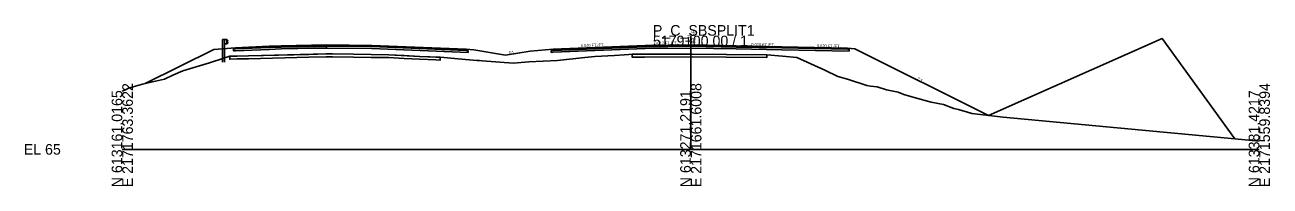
# Model space of a CAD drawing. Extents: x -26 to 1303, y -3010 to 12033.
# Drawn here: x -25.7 to 302.8, y 3990.3 to 4032.8 of the extents above; entities that cross this region are included whole.
import ezdxf

# ---------------------------------------------------------------- set-up
doc = ezdxf.new("R2010")
doc.units = 0
for name, color, linetype in [('RD_GPK_XS_Cell', 7, 'Continuous'), ('RD_PD_Final_TrvlWay', 7, 'Continuous'), ('RD_Sketch10', 7, 'Continuous'), ('RD_XS_Base', 7, 'Continuous'), ('RD_XS_ExGround', 7, 'Continuous'), ('RD_XS_ExPaveRet', 7, 'Continuous'), ('RD_XS_GR', 7, 'Continuous'), ('RD_XS_Greenside', 7, 'Continuous'), ('RD_XS_Pave', 7, 'Continuous'), ('RD_XS_PaveOvlay_CP', 7, 'Continuous'), ('RD_XS_TieSlope', 7, 'Continuous'), ('RD_XS_TX_Elev_EX', 7, 'Continuous'), ('RD_XS_TX_Elev_PR', 7, 'Continuous'), ('RD_XS_TX_Slope', 7, 'Continuous')]:
    doc.layers.add(name, color=color, linetype=linetype)

msp = doc.modelspace()

# ---------------------------------------------------------------- linework, layer by layer
at = {"layer": 'RD_GPK_XS_Cell'}
for p, q in [((150, 4000), (150, 4030)), ((0, 4000), (150, 4000)), ((150, 4000), (300, 4000))]:
    msp.add_line(p, q, dxfattribs=at)
at = {"layer": 'RD_PD_Final_TrvlWay'}
for p, q in [((26.94, 4026.6), (26.44, 4026.56)), ((26.44, 4026.56), (26.44, 4022.99)), ((26.94, 4022.99), (26.94, 4026.6))]:
    msp.add_line(p, q, dxfattribs=at)
at = {"layer": 'RD_Sketch10'}
msp.add_lwpolyline([(228.57, 4008.93), (274.33, 4029.26), (293.53, 4002.78)], dxfattribs=at)
at = {"layer": 'RD_XS_Base'}
for p, q in [((29.75, 4026.51), (29.38, 4026.49)), ((29.38, 4026.49), (29.38, 4026.36)), ((29.38, 4026.36), (29.38, 4025.99)), ((29.38, 4025.99), (29.75, 4026.01)), ((29.88, 4026.51), (29.75, 4026.51)), ((29.75, 4026.01), (29.88, 4026.01)), ((38.75, 4026.87), (29.88, 4026.51)), ((29.88, 4026.01), (38.75, 4026.37)), ((41.88, 4026.99), (38.75, 4026.87)), ((38.75, 4026.37), (41.88, 4026.49)), ((50.75, 4027.17), (41.88, 4026.99)), ((41.88, 4026.49), (50.75, 4026.67)), ((53.88, 4027.23), (50.75, 4027.17)), ((50.75, 4026.67), (53.88, 4026.73)), ((53.88, 4027.35), (53.88, 4027.39)), ((53.88, 4027.39), (53.88, 4027.22)), ((53.88, 4027.23), (53.88, 4027.39)), ((53.88, 4027.39), (53.88, 4027.39)), ((53.88, 4027.39), (53.88, 4027.39)), ((53.88, 4027.39), (53.88, 4026.73)), ((53.88, 4027.23), (53.88, 4027.35)), ((53.88, 4027.1), (53.88, 4027.23)), ((65.88, 4027.1), (53.88, 4027.23)), ((53.88, 4026.73), (53.88, 4027.23)), ((53.88, 4027.23), (53.88, 4027.23)), ((53.88, 4027.23), (53.88, 4027.23)), ((53.88, 4027.22), (53.88, 4026.73)), ((53.88, 4026.73), (53.88, 4027.1)), ((53.88, 4026.73), (65.88, 4026.6)), ((53.88, 4026.73), (53.88, 4026.73)), ((90.75, 4026.1), (65.88, 4027.1)), ((65.88, 4026.6), (91.25, 4025.58)), ((67.88, 4027.02), (67.88, 4027.02)), ((67.88, 4026.52), (67.88, 4026.52)), ((91.25, 4026.08), (90.75, 4026.1)), ((90.75, 4026.1), (90.75, 4026.1)), ((91.25, 4025.58), (91.25, 4026.08)), ((91.25, 4026.08), (91.25, 4026.08)), ((91.25, 4025.58), (91.25, 4025.58)), ((91.25, 4025.58), (91.25, 4025.58)), ((113.15, 4026.09), (113.65, 4026.11)), ((113.15, 4025.59), (113.15, 4026.09)), ((113.15, 4026.09), (113.15, 4026.09)), ((113.65, 4025.61), (113.15, 4025.59)), ((113.15, 4025.59), (113.15, 4025.59)), ((113.15, 4025.59), (113.15, 4025.59)), ((113.65, 4026.11), (138, 4027.09)), ((138, 4026.59), (113.65, 4025.61)), ((113.65, 4026.11), (113.65, 4026.11)), ((113.65, 4025.61), (113.65, 4025.61)), ((136, 4027.01), (136, 4027.01)), ((136, 4026.51), (136, 4026.51)), ((138, 4027.09), (150, 4027.23)), ((150, 4026.73), (138, 4026.59)), ((150, 4027.23), (150, 4027.39)), ((150, 4027.39), (150, 4027.39)), ((150, 4027.39), (150, 4027.39)), ((150, 4027.39), (150, 4026.73)), ((150, 4027.23), (150, 4027.23)), ((162, 4026.99), (150, 4027.23)), ((150, 4027.23), (150, 4027.23)), ((150, 4027.23), (150, 4026.73)), ((150, 4026.73), (150, 4026.73)), ((150, 4026.73), (162, 4026.49)), ((174, 4026.75), (162, 4026.99)), ((162, 4026.99), (162, 4026.99)), ((162, 4026.49), (162, 4026.49)), ((162, 4026.49), (174, 4026.25)), ((191.3, 4026.41), (174, 4026.75)), ((174, 4026.75), (174, 4026.75)), ((174, 4026.25), (174, 4026.25)), ((174, 4026.25), (191.8, 4025.9)), ((191.8, 4026.4), (191.3, 4026.41)), ((191.3, 4026.41), (191.3, 4026.41)), ((191.8, 4025.9), (191.8, 4026.4)), ((191.8, 4026.4), (191.8, 4026.4))]:
    msp.add_line(p, q, dxfattribs=at)
at = {"layer": 'RD_XS_ExGround'}
msp.add_lwpolyline([(0, 4015.32), (0.85, 4015.73), (1.68, 4016.13), (5.29, 4017.16), (7.99, 4017.79), (11.15, 4018.52), (13.38, 4019.57), (15.98, 4020.68), (23, 4022.87), (26.77, 4024.03), (28.34, 4024.55), (30.34, 4024.61), (33.34, 4024.68), (53.81, 4025.19), (61.04, 4025.09), (70.3, 4024.96), (78.39, 4024.54), (83.89, 4024.3), (88.61, 4023.91), (93.52, 4023.47), (94.27, 4023.41), (94.92, 4023.36), (103.13, 4022.78), (107.3, 4023.07), (114.79, 4023.47), (122.03, 4024.26), (124.72, 4024.5), (129.84, 4024.81), (132.42, 4024.96), (133.67, 4025.03), (134.5, 4025.08), (135.83, 4025.09), (137.82, 4025.09), (150.34, 4025.14), (159.37, 4025.06), (170.02, 4024.96), (174.2, 4024.6), (177.94, 4024.23), (185.35, 4020.86), (188.79, 4019.26), (191.3, 4018.5), (196.48, 4016.84), (197.45, 4016.66), (199.13, 4016.49), (201.64, 4015.74), (204.74, 4015.13), (206.23, 4014.5), (208.95, 4013.7), (213.39, 4012.49), (216.7, 4011.88), (219.42, 4010.81), (220.61, 4010.5), (220.64, 4010.5), (223.87, 4009.52), (224.17, 4009.47), (232.37, 4008.47), (293.53, 4002.78), (300, 4002.17)], dxfattribs=at)
at = {"layer": 'RD_XS_ExPaveRet'}
for points in [[(83.89, 4024.3), (83.89, 4024.3), (83.89, 4023.83), (83.89, 4023.55), (83.89, 4023.55), (83.89, 4023.55), (82.7, 4023.6), (78.39, 4023.79), (74.39, 4024), (70.3, 4024.21), (65.63, 4024.28), (61.04, 4024.34), (55.44, 4024.42), (53.81, 4024.44), (49.2, 4024.32), (33.34, 4023.93), (30.34, 4023.86), (28.34, 4023.8), (28.34, 4023.8), (28.34, 4023.8), (28.34, 4023.8), (28.34, 4023.8), (28.34, 4023.8), (28.34, 4024.27), (28.34, 4024.55), (28.34, 4024.55), (28.34, 4024.55), (28.34, 4024.55), (28.34, 4024.55), (28.34, 4024.55), (30.34, 4024.61), (33.34, 4024.68), (49.2, 4025.07), (53.81, 4025.19), (55.44, 4025.17), (61.04, 4025.09), (65.63, 4025.03), (70.3, 4024.96), (74.39, 4024.75), (78.39, 4024.54), (82.7, 4024.35), (83.89, 4024.3), (83.89, 4024.3)], [(82.7, 4024.35), (78.39, 4024.54), (74.39, 4024.75), (70.3, 4024.96), (65.63, 4025.03), (61.04, 4025.09), (55.44, 4025.17), (53.81, 4025.19), (49.2, 4025.07), (33.34, 4024.68), (30.34, 4024.61), (28.34, 4024.55), (28.34, 4024.55), (28.34, 4024.55), (28.34, 4024.55), (28.34, 4024.27), (28.34, 4023.8), (28.34, 4023.8), (28.34, 4023.8), (28.34, 4023.8), (30.34, 4023.86), (33.34, 4023.93), (49.2, 4024.32), (53.81, 4024.44), (55.44, 4024.42), (61.04, 4024.34), (65.63, 4024.28), (70.3, 4024.21), (74.39, 4024), (78.39, 4023.79), (82.7, 4023.6), (83.89, 4023.55), (83.89, 4023.55), (83.89, 4023.83), (83.89, 4024.3), (83.89, 4024.3), (82.7, 4024.35)], [(170.02, 4024.96), (159.37, 4025.06), (159.37, 4025.06), (150.34, 4025.14), (137.82, 4025.09), (137.82, 4025.09), (135.83, 4025.09), (134.5, 4025.08), (134.5, 4025.08), (134.5, 4025.08), (134.5, 4024.33), (134.5, 4024.33), (135.83, 4024.34), (137.82, 4024.34), (137.82, 4024.34), (150.34, 4024.39), (159.37, 4024.31), (159.37, 4024.31), (170.02, 4024.21), (170.02, 4024.21), (170.02, 4024.96), (170.02, 4024.96), (170.02, 4024.96)], [(170.02, 4024.96), (159.37, 4025.06), (150.34, 4025.14), (137.82, 4025.09), (135.83, 4025.09), (134.5, 4025.08), (134.5, 4025.08), (134.5, 4024.33), (134.5, 4024.33), (135.83, 4024.34), (137.82, 4024.34), (150.34, 4024.39), (159.37, 4024.31), (170.02, 4024.21), (170.02, 4024.96)]]:
    msp.add_lwpolyline(points, dxfattribs=at)
at = {"layer": 'RD_XS_GR'}
for p, q in [((26.44, 4026.56), (26.44, 4028.99)), ((26.44, 4028.99), (26.69, 4028.99)), ((26.69, 4028.99), (26.94, 4028.99)), ((26.94, 4028.99), (26.94, 4026.6)), ((26.94, 4027.83), (26.94, 4028.99)), ((26.94, 4028.99), (27.61, 4028.99)), ((27.61, 4027.83), (26.94, 4027.83)), ((27.61, 4028.99), (27.61, 4027.83)), ((27.68, 4028.92), (27.61, 4028.99)), ((27.61, 4028.99), (27.61, 4028.69)), ((27.61, 4028.69), (27.61, 4027.83)), ((27.61, 4028.41), (27.81, 4028.62)), ((27.68, 4028.33), (27.61, 4028.41)), ((27.61, 4027.83), (27.81, 4028.04)), ((27.88, 4028.7), (27.68, 4028.92)), ((27.88, 4028.12), (27.68, 4028.33)), ((27.81, 4028.62), (27.88, 4028.7)), ((27.81, 4028.04), (27.88, 4028.12)), ((26.94, 4026.6), (26.44, 4026.56))]:
    msp.add_line(p, q, dxfattribs=at)
at = {"layer": 'RD_XS_Greenside'}
for p, q in [((24.13, 4026.37), (6.08, 4017.35)), ((92.75, 4026.26), (101.12, 4024.86)), ((107.65, 4025.95), (101.12, 4024.86)), ((193.3, 4026.57), (228.57, 4008.93))]:
    msp.add_line(p, q, dxfattribs=at)
at = {"layer": 'RD_XS_Pave'}
for p, q in [((38.75, 4027.19), (29.88, 4026.83)), ((38.75, 4027.03), (29.88, 4026.67)), ((29.88, 4026.67), (38.75, 4027.03)), ((29.88, 4026.51), (38.75, 4026.87)), ((29.88, 4026.83), (29.88, 4026.79)), ((29.88, 4026.79), (29.88, 4026.67)), ((29.88, 4026.67), (29.88, 4026.63)), ((29.88, 4026.63), (29.88, 4026.51)), ((41.88, 4027.31), (38.75, 4027.19)), ((41.88, 4027.15), (38.75, 4027.03)), ((38.75, 4027.03), (41.88, 4027.15)), ((38.75, 4026.87), (41.88, 4026.99)), ((50.75, 4027.49), (41.88, 4027.31)), ((50.75, 4027.33), (41.88, 4027.15)), ((41.88, 4027.15), (50.75, 4027.33)), ((41.88, 4026.99), (50.75, 4027.17)), ((53.88, 4027.55), (50.75, 4027.49)), ((53.88, 4027.39), (50.75, 4027.33)), ((50.75, 4027.33), (53.88, 4027.39)), ((50.75, 4027.17), (53.88, 4027.23)), ((65.88, 4027.41), (53.88, 4027.55)), ((53.88, 4027.55), (53.88, 4027.55)), ((53.88, 4027.35), (53.88, 4027.39)), ((53.88, 4027.39), (53.88, 4027.35)), ((65.88, 4027.25), (53.88, 4027.39)), ((53.88, 4027.39), (53.88, 4027.39)), ((53.88, 4027.39), (53.88, 4027.23)), ((53.88, 4027.23), (53.88, 4027.39)), ((53.88, 4027.39), (53.88, 4027.39)), ((53.88, 4027.39), (53.88, 4027.39)), ((53.88, 4027.39), (53.88, 4027.39)), ((53.88, 4027.39), (65.88, 4027.25)), ((53.88, 4027.23), (53.88, 4027.35)), ((53.88, 4027.35), (53.88, 4027.23)), ((53.88, 4027.23), (65.88, 4027.1)), ((53.88, 4027.23), (53.88, 4027.23)), ((90.75, 4026.42), (65.88, 4027.41)), ((90.75, 4026.26), (65.88, 4027.25)), ((65.88, 4027.25), (90.75, 4026.26)), ((65.88, 4027.1), (90.75, 4026.1)), ((67.88, 4027.33), (67.88, 4027.33)), ((67.88, 4027.17), (67.88, 4027.17)), ((67.88, 4027.17), (67.88, 4027.17)), ((67.88, 4027.02), (67.88, 4027.02)), ((90.75, 4026.26), (90.75, 4026.42)), ((90.75, 4026.42), (90.75, 4026.42)), ((90.75, 4026.1), (90.75, 4026.26)), ((90.75, 4026.26), (90.75, 4026.26)), ((90.75, 4026.26), (90.75, 4026.26)), ((90.75, 4026.26), (90.75, 4026.26)), ((90.75, 4026.1), (90.75, 4026.1)), ((90.75, 4026.1), (90.75, 4026.1)), ((138, 4027.41), (113.65, 4026.43)), ((138, 4027.25), (113.65, 4026.27)), ((113.65, 4026.27), (138, 4027.25)), ((113.65, 4026.11), (138, 4027.09)), ((113.65, 4026.43), (113.65, 4026.43)), ((113.65, 4026.43), (113.65, 4026.27)), ((113.65, 4026.27), (113.65, 4026.27)), ((113.65, 4026.27), (113.65, 4026.11)), ((113.65, 4026.27), (113.65, 4026.27)), ((113.65, 4026.27), (113.65, 4026.27)), ((113.65, 4026.11), (113.65, 4026.11)), ((113.65, 4026.11), (113.65, 4026.11)), ((136, 4027.33), (136, 4027.33)), ((136, 4027.17), (136, 4027.17)), ((136, 4027.17), (136, 4027.17)), ((136, 4027.01), (136, 4027.01)), ((150, 4027.55), (138, 4027.41)), ((150, 4027.39), (138, 4027.25)), ((138, 4027.25), (150, 4027.39)), ((138, 4027.09), (150, 4027.23)), ((162, 4027.31), (150, 4027.55)), ((150, 4027.55), (150, 4027.55)), ((150, 4027.23), (150, 4027.39)), ((150, 4027.39), (150, 4027.39)), ((150, 4027.39), (150, 4027.39)), ((150, 4027.39), (162, 4027.15)), ((162, 4027.15), (150, 4027.39)), ((150, 4027.39), (150, 4027.39)), ((150, 4027.39), (150, 4027.39)), ((150, 4027.39), (150, 4027.23)), ((150, 4027.23), (150, 4027.23)), ((150, 4027.23), (162, 4026.99)), ((174, 4027.07), (162, 4027.31)), ((162, 4027.31), (162, 4027.31)), ((162, 4027.15), (162, 4027.15)), ((162, 4027.15), (174, 4026.91)), ((174, 4026.91), (162, 4027.15)), ((162, 4027.15), (162, 4027.15)), ((162, 4026.99), (162, 4026.99)), ((162, 4026.99), (174, 4026.75)), ((191.3, 4026.73), (174, 4027.07)), ((174, 4027.07), (174, 4027.07)), ((174, 4026.91), (174, 4026.91)), ((174, 4026.91), (191.3, 4026.57)), ((191.3, 4026.57), (174, 4026.91)), ((174, 4026.91), (174, 4026.91)), ((174, 4026.75), (191.3, 4026.41)), ((174, 4026.75), (174, 4026.75)), ((191.3, 4026.57), (191.3, 4026.73)), ((191.3, 4026.73), (191.3, 4026.73)), ((191.3, 4026.41), (191.3, 4026.57)), ((191.3, 4026.57), (191.3, 4026.57))]:
    msp.add_line(p, q, dxfattribs=at)
at = {"layer": 'RD_XS_PaveOvlay_CP'}
for p, q in [((29.88, 4026.83), (41.88, 4027.31)), ((41.88, 4027.31), (53.88, 4027.55)), ((65.88, 4027.41), (53.88, 4027.55)), ((53.88, 4027.55), (53.88, 4027.55)), ((90.75, 4026.42), (65.88, 4027.41)), ((67.88, 4027.33), (67.88, 4027.33)), ((90.75, 4026.42), (90.75, 4026.42)), ((138, 4027.41), (113.65, 4026.43)), ((113.65, 4026.43), (113.65, 4026.43)), ((136, 4027.33), (136, 4027.33)), ((150, 4027.55), (138, 4027.41)), ((162, 4027.31), (150, 4027.55)), ((150, 4027.55), (150, 4027.55)), ((174, 4027.07), (162, 4027.31)), ((162, 4027.31), (162, 4027.31)), ((191.3, 4026.73), (174, 4027.07)), ((174, 4027.07), (174, 4027.07))]:
    msp.add_line(p, q, dxfattribs=at)
at = {"layer": 'RD_XS_TieSlope'}
for p, q in [((29.88, 4026.83), (24.13, 4026.37)), ((90.75, 4026.42), (92.75, 4026.26)), ((113.65, 4026.43), (107.65, 4025.95)), ((191.3, 4026.73), (193.3, 4026.57))]:
    msp.add_line(p, q, dxfattribs=at)

# ---------------------------------------------------------------- texts
at = {"layer": 'RD_GPK_XS_Cell'}
for s, p in [('P_C_SBSPLIT1', (140, 4030)), ('5179+00.00 / 1', (140, 4027.2)), ('EL 65', (-26, 3998.6))]:
    msp.add_text(s, height=2.8, dxfattribs=at).set_placement(p)
for s, p in [('N 613161.0165', (0, 3990)), ('E 2171763.3622', (2.8, 3990)), ('N 613271.2191', (150, 3990)), ('E 2171661.6008', (152.8, 3990)), ('N 613381.4217', (300, 3990)), ('E 2171559.8394', (302.8, 3990))]:
    msp.add_text(s, height=2.8, rotation=90, dxfattribs=at).set_placement(p)
at = {"layer": 'RD_XS_TX_Elev_EX'}
msp.add_text('90.14', height=0.6, rotation=90, dxfattribs=at).set_placement((149.74, 4028.18))
at = {"layer": 'RD_XS_TX_Elev_PR'}
msp.add_text('92.55', height=1, rotation=90, dxfattribs=at).set_placement((151.19, 4027.93))
at = {"layer": 'RD_XS_TX_Slope'}
for s, rotation, p in [('0.040 FT./FT.', 2.2906, (120.96, 4026.99)), ('0.012 FT./FT.', 0.6906, (140.36, 4027.66)), ('0.020 FT./FT.', 358.8542, (165.94, 4027.33)), ('6:1', 9.4623, (102, 4025.07)), ('0.020 FT./FT.', 358.8542, (183.25, 4026.98)), ('2:1', 333.4349, (209.69, 4018.43))]:
    msp.add_text(s, height=0.75, rotation=rotation, dxfattribs=at).set_placement(p)

doc.saveas('drawing.dxf')
